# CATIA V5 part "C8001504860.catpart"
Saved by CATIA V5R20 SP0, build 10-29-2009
Part number: C8001504860
Source: Unknown
Property "A": "70"
Property "ARTICLENO": "C8001504860"
Property "B": "32"
Property "BOMINFO": "C8001504860"
Property "C": "120"
Property "CA": "C8001504860"
Property "D1": "120"
Property "DES": "ROTATING EYEBOLT WITH RING Ton 15 M48x60"
Property "E": "130"
Property "H": "280"
Property "L": "60"
Property "LINA": "C8001504860"
Property "NB": "C8001504860"
Property "NBSYN": "$CODE."
Property "NN": "C800"
Property "NT": "Rotating eyebolt with ring"
Property "SIZE": "M48"
Property "SUPPLIER": "CF"
Property "SW": "95"
Property "WEIGHT": "10000"
Property "WLL": "15.00"
Bounding box of the stored display mesh (mm): x -67 to 67, y -60 to 311.813, z -60 to 60
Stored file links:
  C:\Users\Utente\Desktop\3D files 800\C8001504860.catpart
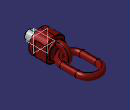
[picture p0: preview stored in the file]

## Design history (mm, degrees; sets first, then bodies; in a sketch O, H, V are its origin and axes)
Body1 "Geometry.1" (main body)
  Solid1 "C8001504860.catpart": solid without history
